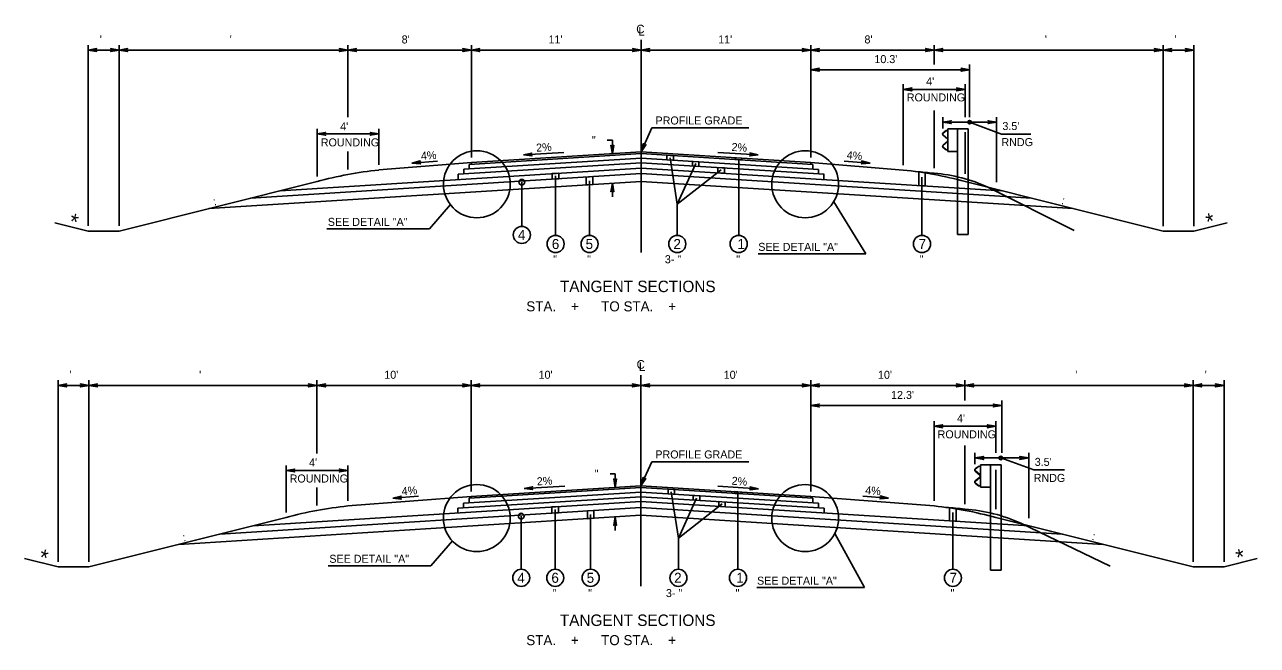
# Model space of a CAD drawing. Extents: x -540 to 1231, y -564 to 421.
# Drawn here: x -106.3 to 108.9, y -310 to -201.7 of the extents above; entities that cross this region are included whole.
import ezdxf

# ---------------------------------------------------------------- set-up
doc = ezdxf.new("R2010")
doc.units = 0
doc.layers.add('1', color=7, linetype='Continuous')
doc.layers.add('Des_ Drain_ Ftrs', color=7, linetype='Continuous')

msp = doc.modelspace()

# ---------------------------------------------------------------- linework, layer by layer
at = {"layer": '1'}
for p, q in [((1.3, -241.47), (1.3, -204.38)), ((-95.24, -236.84), (-95.24, -205.26)), ((-89.85, -206.14), (-95.24, -206.14)), ((-89.85, -236.84), (-89.85, -205.26)), ((-49.89, -206.14), (-89.85, -206.14)), ((-49.89, -217.88), (-49.89, -205.26)), ((-28.33, -206.14), (-49.89, -206.14)), ((-28.33, -224.9), (-28.33, -205.26)), ((1.3, -206.14), (-28.33, -206.14)), ((1.3, -206.14), (30.94, -206.14)), ((30.94, -224.9), (30.94, -205.26)), ((30.94, -206.14), (52.49, -206.14)), ((52.49, -208.69), (52.49, -205.26)), ((52.49, -206.14), (92.45, -206.14)), ((92.45, -236.85), (92.45, -205.26)), ((92.45, -206.14), (97.84, -206.14)), ((97.84, -236.85), (97.84, -205.26)), ((58.68, -217.84), (58.68, -208.69)), ((30.93, -209.57), (58.68, -209.57)), ((-89.85, -233.73), (-89.85, -212.26)), ((47.1, -226.2), (47.1, -212.12)), ((47.1, -213), (57.88, -213)), ((57.88, -217.84), (57.88, -212.12)), ((52.49, -226.75), (52.49, -216.67)), ((53.99, -219.8), (53.99, -217.84)), ((53.99, -218.72), (63.37, -218.72)), ((58.68, -218.72), (64.24, -220.8)), ((63.37, -229.21), (63.37, -217.84)), ((-55.26, -228.2), (-55.26, -219.89)), ((-44.49, -220.77), (-55.26, -220.77)), ((-44.49, -226.19), (-44.49, -219.89)), ((1.3, -223.92), (3.21, -219.72)), ((20.13, -219.72), (3.21, -219.72)), ((54.06, -221.01), (54.79, -221.65)), ((54.59, -220.19), (54.07, -220.58)), ((54.08, -220.99), (54.81, -221.63)), ((54.6, -220.22), (54.09, -220.61)), ((54.9, -220.14), (54.59, -220.19)), ((54.9, -220.17), (54.6, -220.22)), ((54.9, -219.91), (54.9, -223.84)), ((54.9, -219.91), (56.59, -219.91)), ((56.59, -219.91), (56.59, -238.31)), ((58.41, -219.91), (56.59, -219.91)), ((57.88, -227.72), (57.88, -220.48)), ((58.41, -219.91), (58.41, -238.31)), ((64.24, -220.8), (69.39, -220.8)), ((-49.89, -226.97), (-49.89, -223.83)), ((-3.71, -221.86), (-4.59, -221.86)), ((-3.71, -221.86), (-3.71, -224.23)), ((54.79, -222.1), (54.06, -222.74)), ((54.07, -223.17), (54.59, -223.56)), ((54.81, -222.12), (54.08, -222.76)), ((54.09, -223.14), (54.6, -223.53)), ((54.59, -223.56), (54.9, -223.61)), ((54.6, -223.53), (54.9, -223.58)), ((54.87, -221.84), (54.87, -221.91)), ((54.9, -221.84), (54.9, -221.91)), ((54.9, -223.84), (56.59, -223.84)), ((-44.49, -227.07), (-28.33, -225.77)), ((-38.7, -225.86), (-34.22, -225.5)), ((-30.64, -227.81), (1.3, -225.8)), ((-29.67, -226.95), (1.3, -225.01)), ((-28.69, -226.1), (1.3, -224.21)), ((-28.33, -225.77), (1.3, -223.91)), ((-28.33, -226.07), (-28.33, -225.77)), ((-12.16, -224), (-19.24, -224.45)), ((30.94, -225.78), (1.3, -223.92)), ((31.3, -226.1), (1.3, -224.21)), ((32.27, -226.96), (1.3, -225.01)), ((33.26, -227.82), (1.3, -225.81)), ((5.83, -224.5), (5.83, -225.29)), ((6.4, -224.95), (7.63, -233.04)), ((10.85, -225.95), (7.63, -233.04)), ((14.71, -224), (21.78, -224.45)), ((18.35, -225.16), (18.35, -238.5)), ((47.1, -227.08), (30.94, -225.78)), ((30.94, -226.08), (30.94, -225.78)), ((41.29, -225.86), (36.8, -225.5)), ((-66.88, -231.98), (1.3, -227.7)), ((-61.71, -230.69), (1.3, -226.73)), ((-30.64, -227.81), (-30.64, -228.74)), ((-29.67, -226.95), (-29.67, -227.75)), ((-28.69, -226.1), (-28.69, -226.89)), ((-13.62, -228.11), (-13.62, -238.5)), ((64.32, -230.7), (1.3, -226.73)), ((69.48, -231.99), (1.3, -227.7)), ((15.3, -227.04), (7.63, -233.04)), ((31.3, -226.1), (31.3, -226.88)), ((32.27, -226.96), (32.27, -227.75)), ((33.24, -227.82), (33.24, -228.74)), ((53.99, -227.86), (53.99, -227.86)), ((-55.26, -229.08), (-89.85, -237.72)), ((-74.17, -233.8), (1.3, -229.06)), ((-19.52, -229.2), (-19.52, -236.91)), ((-7.69, -228.94), (-7.69, -238.5)), ((-3.71, -229.38), (-3.71, -231.75)), ((76.77, -233.81), (1.3, -229.06)), ((50.36, -228.33), (50.36, -238.5)), ((57.88, -229.09), (92.45, -237.73)), ((61.87, -230.09), (76.93, -237.61)), ((-35.65, -237.32), (-32, -233.1)), ((7.63, -233.04), (7.63, -238.5)), ((34.95, -232.6), (40.55, -241.68)), ((-101.07, -236.26), (-95.24, -237.72)), ((103.67, -236.27), (97.84, -237.73)), ((-89.85, -237.72), (-95.24, -237.72)), ((-53.58, -237.32), (-35.65, -237.32)), ((58.41, -238.31), (56.59, -238.31)), ((92.45, -237.73), (97.84, -237.73)), ((21.76, -241.68), (40.55, -241.68)), ((-100.51, -295.43), (-100.51, -263.77)), ((-95.12, -264.65), (-100.51, -264.65)), ((-95.12, -295.43), (-95.12, -263.77)), ((-55.29, -264.65), (-95.12, -264.65)), ((-55.29, -276.52), (-55.29, -263.77)), ((-28.34, -264.65), (-55.29, -264.65)), ((-28.34, -283.15), (-28.34, -263.77)), ((1.29, -264.65), (-28.34, -264.65)), ((1.29, -299.71), (1.29, -262.89)), ((1.29, -264.65), (30.93, -264.65)), ((30.93, -283.15), (30.93, -263.77)), ((30.93, -264.65), (57.87, -264.65)), ((57.87, -267.29), (57.87, -263.77)), ((57.87, -264.65), (97.71, -264.65)), ((97.71, -295.43), (97.71, -263.77)), ((97.71, -264.65), (103.1, -264.65)), ((103.1, -295.43), (103.1, -263.77)), ((30.92, -268.17), (64.29, -268.17)), ((64.29, -276.44), (64.29, -267.29)), ((52.48, -284.81), (52.48, -270.91)), ((63.25, -276.44), (63.25, -270.91)), ((52.48, -271.79), (63.25, -271.79)), ((57.87, -285.35), (57.87, -275.15)), ((59.6, -278.39), (59.6, -276.44)), ((59.6, -277.32), (68.99, -277.32)), ((64.12, -277.32), (69.88, -279.4)), ((68.99, -287.81), (68.99, -276.44)), ((-60.66, -286.82), (-60.66, -278.62)), ((-49.89, -279.5), (-60.66, -279.5)), ((-49.89, -284.81), (-49.89, -278.62)), ((1.29, -282.16), (3.19, -277.99)), ((20.11, -277.99), (3.19, -277.99)), ((59.67, -279.61), (60.43, -280.25)), ((60.22, -278.79), (59.69, -279.18)), ((59.69, -279.59), (60.45, -280.23)), ((60.23, -278.82), (59.7, -279.2)), ((60.55, -278.74), (60.22, -278.79)), ((60.55, -278.77), (60.23, -278.82)), ((60.55, -278.51), (60.55, -282.44)), ((60.55, -278.51), (62.3, -278.51)), ((62.3, -278.51), (62.3, -296.9)), ((64.19, -278.51), (62.3, -278.51)), ((63.25, -286.27), (63.25, -279.39)), ((64.19, -278.51), (64.19, -296.9)), ((69.88, -279.4), (75.23, -279.4)), ((-3.21, -280.08), (-4.09, -280.08)), ((-3.21, -280.08), (-3.21, -282.45)), ((60.43, -280.7), (59.67, -281.33)), ((60.45, -280.72), (59.69, -281.36)), ((59.69, -281.77), (60.22, -282.16)), ((59.7, -281.74), (60.23, -282.13)), ((60.52, -280.44), (60.52, -280.51)), ((60.55, -280.44), (60.55, -280.51)), ((-55.29, -285.59), (-55.29, -282.47)), ((-49.89, -285.69), (-28.35, -284.03)), ((-42.06, -284.34), (-37.58, -283.99)), ((-30.69, -286.09), (1.29, -284.08)), ((-29.7, -285.22), (1.29, -283.27)), ((-28.71, -284.35), (1.29, -282.46)), ((-28.35, -284.03), (1.29, -282.16)), ((-28.35, -284.33), (-28.35, -284.03)), ((-12.03, -282.22), (-19.11, -282.67)), ((30.93, -284.03), (1.29, -282.16)), ((31.29, -284.35), (1.29, -282.46)), ((32.28, -285.22), (1.29, -283.27)), ((33.28, -286.09), (1.29, -284.08)), ((6.59, -283.2), (7.83, -291.3)), ((14.72, -282.25), (21.8, -282.7)), ((18.23, -283.41), (18.23, -296.74)), ((30.93, -284.33), (30.93, -284.03)), ((52.48, -285.69), (30.93, -284.03)), ((44.53, -284.31), (40.04, -283.97)), ((60.22, -282.16), (60.55, -282.21)), ((60.23, -282.13), (60.55, -282.18)), ((60.55, -282.44), (62.3, -282.44)), ((-72.23, -290.59), (1.29, -285.97)), ((-66.46, -289.15), (1.29, -284.89)), ((-30.69, -286.09), (-30.69, -286.9)), ((-29.7, -285.22), (-29.7, -286.03)), ((-28.71, -284.35), (-28.71, -285.16)), ((69.05, -289.15), (1.29, -284.89)), ((74.82, -290.59), (1.29, -285.97)), ((10.99, -284.33), (7.83, -291.3)), ((15.44, -285.34), (7.83, -291.3)), ((31.29, -284.35), (31.29, -285.16)), ((32.28, -285.22), (32.28, -286.04)), ((33.27, -286.09), (33.27, -286.91)), ((-60.66, -287.7), (-95.12, -296.31)), ((-79.44, -292.39), (1.29, -287.32)), ((-19.62, -287.45), (-19.62, -296.74)), ((-13.68, -286.33), (-13.68, -296.74)), ((-7.5, -287.16), (-7.5, -296.74)), ((-3.21, -287.6), (-3.21, -289.97)), ((82.02, -292.39), (1.29, -287.32)), ((55.76, -286.84), (55.76, -296.74)), ((59.6, -286.45), (59.6, -286.45)), ((63.25, -287.7), (97.71, -296.31)), ((35.13, -290.51), (40.33, -299.94)), ((67.6, -288.69), (83.22, -296.21)), ((-35.38, -296.12), (-31.64, -291.8)), ((7.83, -291.3), (7.83, -296.74)), ((-106.34, -294.85), (-100.51, -296.31)), ((108.92, -294.86), (103.1, -296.31)), ((-95.12, -296.31), (-100.51, -296.31)), ((-53.31, -296.12), (-35.38, -296.12)), ((64.19, -296.9), (62.3, -296.9)), ((97.71, -296.31), (103.1, -296.31)), ((21.55, -299.94), (40.33, -299.94))]:
    msp.add_line(p, q, dxfattribs=at)
for points in [[(5.83, -224.5), (6.97, -224.57), (6.97, -225.37), (5.83, -225.29)], [(10.28, -225.57), (11.42, -225.65), (11.42, -226.44), (10.28, -226.37)], [(17.78, -224.95), (18.92, -225.03), (18.92, -225.32), (17.78, -225.25)], [(-14.19, -227.7), (-13.04, -227.63), (-13.04, -228.6), (-14.19, -228.67)], [(14.72, -227.58), (14.72, -226.65), (15.87, -226.72), (15.87, -227.65)], [(49.79, -227.41), (50.92, -227.58), (50.92, -229.86), (49.79, -229.78)], [(-8.26, -228.3), (-7.11, -228.23), (-7.11, -229.59), (-8.26, -229.66)], [(6.02, -282.76), (7.17, -282.83), (7.17, -283.64), (6.02, -283.57)], [(10.41, -283.85), (11.56, -283.92), (11.56, -284.73), (10.41, -284.65)], [(17.66, -283.19), (18.81, -283.26), (18.81, -283.56), (17.66, -283.49)], [(-14.26, -285.87), (-13.11, -285.79), (-13.11, -286.87), (-14.26, -286.95)], [(14.86, -284.93), (16.01, -285.01), (16.01, -285.82), (14.86, -285.74)], [(55.18, -288.28), (55.18, -286.04), (56.33, -286.2), (56.33, -288.35)], [(-8.07, -286.56), (-6.93, -286.49), (-6.93, -287.83), (-8.07, -287.91)]]:
    msp.add_lwpolyline(points, close=True, dxfattribs=at)
for centre, radius in [((58.68, -218.73), 0.3), ((-27.37, -229.56), 5.84), ((29.97, -229.56), 5.84), ((-19.52, -229.2), 0.5), ((-19.52, -238.4), 1.49), ((-13.62, -239.98), 1.49), ((-7.69, -239.98), 1.49), ((7.63, -239.98), 1.49), ((18.35, -239.98), 1.49), ((50.36, -239.98), 1.49), ((-27.38, -287.8), 5.84), ((29.96, -287.8), 5.84), ((-19.62, -287.45), 0.5), ((-19.62, -298.23), 1.49), ((-13.68, -298.23), 1.49), ((-7.5, -298.23), 1.49), ((7.83, -298.23), 1.49), ((18.23, -298.23), 1.49), ((55.76, -298.23), 1.49)]:
    msp.add_circle(centre, radius, dxfattribs=at)
for centre, radius, start, end in [((54.24, -220.8), 0.278, 126.9799, 229.021), ((54.24, -220.8), 0.249, 126.9799, 229.021), ((54.62, -221.84), 0.249, 0, 49.0365), ((54.62, -221.84), 0.278, 0, 49.0365), ((54.24, -222.95), 0.278, 130.979, 233.0201), ((54.24, -222.95), 0.249, 130.979, 233.0201), ((54.62, -221.91), 0.249, 310.9635, 0), ((54.62, -221.91), 0.278, 310.9635, 0), ((-37.61, -293.91), 67.19, 95.8795, 105.2381), ((40.22, -293.91), 67.19, 74.7619, 84.1205), ((41.67, -328.3), 101.24, 83.8633, 85.6775), ((50.37, -254.92), 27.37, 65.1374, 85.5513), ((-43.01, -352.53), 67.19, 95.8795, 105.2381), ((45.59, -352.53), 67.19, 74.7598, 84.1183)]:
    msp.add_arc(centre, radius, start, end, dxfattribs=at)
msp.add_ellipse((64.12, -277.32), major_axis=(-0.311, 0), ratio=0.964041, dxfattribs=at)
for centre, major_axis, start_param, end_param in [((59.86, -279.4), (-0.288, 0), 5.35781, 7.138763), ((59.86, -279.4), (-0.258, 0), 5.35781, 7.138763), ((59.86, -281.54), (-0.288, 0), 5.427608, 7.208561), ((59.86, -281.54), (-0.258, 0), 5.427608, 7.208561), ((60.26, -280.44), (0.258, 0), 0, 0.855848), ((60.26, -280.51), (0.258, 0), 5.427337, 6.283185), ((60.26, -280.44), (0.288, 0), 0, 0.855848), ((60.26, -280.51), (0.288, 0), 5.427337, 6.283185), ((46.64, -386.9), (105.02, 0), 1.463691, 1.495354), ((55.67, -313.52), (28.39, 0), 1.136862, 1.493152)]:
    msp.add_ellipse(centre, major_axis=major_axis, ratio=0.964041, start_param=start_param, end_param=end_param, dxfattribs=at)
at = {"layer": 'Des_ Drain_ Ftrs'}
for points in [[(-95.24, -206.14), (-93.76, -206.39), (-94.05, -206.14), (-93.76, -205.89)], [(-89.85, -206.14), (-91.34, -206.39), (-91.05, -206.14), (-91.34, -205.89)], [(-89.85, -206.14), (-88.37, -206.39), (-88.66, -206.14), (-88.37, -205.89)], [(-49.89, -206.14), (-51.38, -206.39), (-51.08, -206.14), (-51.38, -205.89)], [(-49.89, -206.14), (-48.4, -206.39), (-48.69, -206.14), (-48.4, -205.89)], [(-28.33, -206.14), (-29.82, -206.39), (-29.53, -206.14), (-29.82, -205.89)], [(-28.33, -206.14), (-26.85, -206.39), (-27.14, -206.14), (-26.85, -205.89)], [(1.3, -206.14), (-0.19, -206.39), (0.11, -206.14), (-0.19, -205.89)], [(1.3, -206.14), (2.79, -206.39), (2.5, -206.14), (2.79, -205.89)], [(30.94, -206.14), (29.45, -206.39), (29.74, -206.14), (29.45, -205.89)], [(30.94, -206.14), (32.43, -206.39), (32.13, -206.14), (32.43, -205.89)], [(52.49, -206.14), (51, -206.39), (51.3, -206.14), (51, -205.89)], [(52.49, -206.14), (53.98, -206.39), (53.68, -206.14), (53.98, -205.89)], [(92.45, -206.14), (90.96, -206.39), (91.26, -206.14), (90.96, -205.89)], [(92.45, -206.14), (93.94, -206.39), (93.65, -206.14), (93.94, -205.89)], [(97.84, -206.14), (96.35, -206.39), (96.65, -206.14), (96.35, -205.89)], [(30.93, -209.57), (32.42, -209.82), (32.13, -209.57), (32.42, -209.32)], [(58.68, -209.57), (57.19, -209.82), (57.49, -209.57), (57.19, -209.32)], [(47.1, -213), (48.59, -213.25), (48.29, -213), (48.59, -212.75)], [(57.88, -213), (56.39, -213.25), (56.68, -213), (56.39, -212.75)], [(53.99, -218.72), (55.48, -218.97), (55.18, -218.72), (55.48, -218.48)], [(63.37, -218.72), (61.89, -218.97), (62.18, -218.72), (61.89, -218.48)], [(-55.26, -220.77), (-53.78, -221.02), (-54.07, -220.77), (-53.78, -220.52)], [(-44.49, -220.77), (-45.98, -221.02), (-45.68, -220.77), (-45.98, -220.52)], [(-3.71, -224.23), (-3.46, -222.74), (-3.71, -223.04), (-3.96, -222.74)], [(1.3, -223.92), (2.14, -222.67), (1.8, -222.83), (1.69, -222.46)], [(-38.7, -225.86), (-37.2, -225.99), (-37.51, -225.76), (-37.24, -225.49)], [(-19.24, -224.45), (-17.73, -224.6), (-18.04, -224.37), (-17.77, -224.11)], [(21.78, -224.45), (20.28, -224.6), (20.59, -224.37), (20.31, -224.1)], [(41.29, -225.86), (39.78, -225.99), (40.1, -225.76), (39.82, -225.49)], [(-3.71, -229.38), (-3.46, -230.87), (-3.71, -230.58), (-3.96, -230.87)], [(-100.51, -264.65), (-99.02, -264.9), (-99.31, -264.65), (-99.02, -264.4)], [(-95.12, -264.65), (-96.61, -264.9), (-96.31, -264.65), (-96.61, -264.4)], [(-95.12, -264.65), (-93.63, -264.9), (-93.93, -264.65), (-93.63, -264.4)], [(-55.29, -264.65), (-56.77, -264.9), (-56.48, -264.65), (-56.77, -264.4)], [(-55.29, -264.65), (-53.8, -264.9), (-54.09, -264.65), (-53.8, -264.4)], [(-28.34, -264.65), (-29.83, -264.9), (-29.54, -264.65), (-29.83, -264.4)], [(-28.34, -264.65), (-26.86, -264.9), (-27.15, -264.65), (-26.86, -264.4)], [(1.29, -264.65), (-0.2, -264.9), (0.1, -264.65), (-0.2, -264.4)], [(1.29, -264.65), (2.78, -264.9), (2.48, -264.65), (2.78, -264.4)], [(30.93, -264.65), (29.44, -264.9), (29.73, -264.65), (29.44, -264.4)], [(30.93, -264.65), (32.41, -264.9), (32.12, -264.65), (32.41, -264.4)], [(57.87, -264.65), (56.38, -264.9), (56.67, -264.65), (56.38, -264.4)], [(57.87, -264.65), (59.36, -264.9), (59.06, -264.65), (59.36, -264.4)], [(97.71, -264.65), (96.22, -264.9), (96.51, -264.65), (96.22, -264.4)], [(97.71, -264.65), (99.2, -264.9), (98.9, -264.65), (99.2, -264.4)], [(103.1, -264.65), (101.61, -264.9), (101.9, -264.65), (101.61, -264.4)], [(30.92, -268.17), (32.41, -268.42), (32.12, -268.17), (32.41, -267.92)], [(64.29, -268.17), (62.8, -268.42), (63.1, -268.17), (62.8, -267.92)], [(52.48, -271.79), (53.97, -272.04), (53.67, -271.79), (53.97, -271.55)], [(63.25, -271.79), (61.77, -272.04), (62.06, -271.79), (61.77, -271.55)], [(59.6, -277.32), (61.15, -277.57), (60.84, -277.32), (61.15, -277.08)], [(68.99, -277.32), (67.44, -277.57), (67.75, -277.32), (67.44, -277.08)], [(-60.66, -279.5), (-59.18, -279.75), (-59.47, -279.5), (-59.18, -279.25)], [(-49.89, -279.5), (-51.38, -279.75), (-51.08, -279.5), (-51.38, -279.25)], [(-3.21, -282.45), (-2.97, -280.96), (-3.21, -281.25), (-3.46, -280.96)], [(1.29, -282.16), (2.13, -280.91), (1.78, -281.08), (1.68, -280.7)], [(-42.06, -284.34), (-40.56, -284.48), (-40.87, -284.25), (-40.6, -283.98)], [(-19.11, -282.67), (-17.61, -282.82), (-17.92, -282.59), (-17.64, -282.33)], [(21.8, -282.7), (20.3, -282.85), (20.61, -282.62), (20.33, -282.36)], [(44.53, -284.31), (43.02, -284.45), (43.34, -284.22), (43.06, -283.95)], [(-3.21, -287.6), (-2.97, -289.09), (-3.21, -288.79), (-3.46, -289.09)]]:
    msp.add_lwpolyline(points, close=True, dxfattribs=at)

# ---------------------------------------------------------------- texts
at = {"layer": '1'}
for s, height, p in [(" '", 1.4, (-93.74, -204.99)), ("  '", 1.4, (-71.57, -204.99)), ("8'", 1.4, (-40.5, -204.99)), ("11'", 1.4, (-14.86, -204.99)), ("11'", 1.4, (14.77, -204.99)), ("8'", 1.4, (40.32, -204.99)), ("  '", 1.4, (70.78, -204.99)), (" '", 1.4, (93.95, -204.99)), ("10.3'", 1.4, (42.05, -208.42)), ("4'", 1.4, (51.1, -212.3)), ('ROUNDING', 1.4, (47.71, -215.1)), ("4'", 1.4, (-51.23, -220.15)), ('PROFILE GRADE', 1.4, (3.83, -219.13)), ("3.5'", 1.4, (64.4, -220.1)), ('ROUNDING', 1.4, (-54.62, -222.95)), ('RNDG', 1.4, (64.23, -222.9)), ('SEE DETAIL "A"', 1.4, (-53.39, -236.82)), ('4', 1.75, (-20.2, -239.27)), ('6', 1.75, (-14.28, -240.86)), ('5', 1.75, (-8.38, -240.86)), ('2', 1.75, (6.96, -240.86)), ('1', 1.75, (18.14, -240.86)), ('SEE DETAIL "A"', 1.4, (21.77, -241.18)), ('7', 1.75, (49.77, -240.86)), (' "', 1.4, (-14.56, -243.34)), (' "', 1.4, (-8.63, -243.34)), ('3- "', 1.4, (5.46, -243.34)), (' "', 1.4, (17.41, -243.34)), ('  "', 1.4, (48.92, -243.34)), ('TANGENT SECTIONS', 2, (-12.87, -248.38)), ('STA.    +      TO STA.    +     ', 1.75, (-18.73, -251.74)), (" '", 1.4, (-99.01, -263.5)), ("  '", 1.4, (-76.9, -263.5)), ("10'", 1.4, (-43.53, -263.5)), ("10'", 1.4, (-16.59, -263.5)), ("10'", 1.4, (15.74, -263.5)), ("10'", 1.4, (42.68, -263.5)), ("  '", 1.4, (76.09, -263.5)), (" '", 1.4, (99.21, -263.5)), ("12.3'", 1.4, (44.96, -267.02)), ("4'", 1.4, (56.48, -271.09)), ('ROUNDING', 1.4, (53.09, -273.89)), ("4'", 1.4, (-56.67, -278.8)), ('PROFILE GRADE', 1.4, (3.8, -277.4)), ("3.5'", 1.4, (70.05, -278.7)), ('ROUNDING', 1.4, (-60.06, -281.6)), ('RNDG', 1.4, (69.87, -281.5)), ('SEE DETAIL "A"', 1.4, (-53.13, -295.61)), ('4', 1.75, (-20.29, -299.1)), ('6', 1.75, (-14.35, -299.1)), ('5', 1.75, (-8.19, -299.1)), ('2', 1.75, (7.08, -299.1)), ('1', 1.75, (17.93, -299.1)), ('SEE DETAIL "A"', 1.4, (21.56, -299.43)), ('7', 1.75, (55.17, -299.1)), (' "', 1.4, (-14.63, -301.59)), (' "', 1.4, (-8.45, -301.59)), ('3- "', 1.4, (5.65, -301.59)), (' "', 1.4, (17.29, -301.59)), ('  "', 1.4, (54.31, -301.59)), ('TANGENT SECTIONS', 2, (-12.88, -306.63)), ('STA.    +      TO STA.    +     ', 1.75, (-18.74, -309.98))]:
    msp.add_text(s, height=height, dxfattribs=at).set_placement(p)
for s, height, rotation, p in [('  "', 1.4, 0.1438, (-8.32, -222.56)), ('4%', 1.4, 4.8672, (-37.08, -225.34)), ('2%', 1.4, 3.7237, (-16.97, -223.89)), ('2%', 1.4, 356.2763, (17.07, -223.73)), ('4%', 1.4, 355.1257, (37.17, -225.13)), (' : ', 1.4, 14.2282, (-73.74, -233.41)), (' : ', 1.4, 345.7718, (74.11, -232.86)), ('*', 2.8, 12.8479, (100.3, -237.54)), ('*', 2.8, 347.1521, (-98.76, -237.29)), ('  "', 1.4, 0.1438, (-7.83, -280.78)), ('2%', 1.4, 3.7237, (-16.85, -282.11)), ('2%', 1.4, 356.2768, (17.09, -281.98)), ('4%', 1.4, 4.703, (-40.44, -283.83)), ('4%', 1.4, 355.2917, (40.41, -283.6)), (' : ', 1.4, 345.7718, (79.43, -291.46)), (' : ', 1.4, 14.2282, (-79.07, -292.02)), ('*', 2.8, 347.1521, (-104.02, -295.88)), ('*', 2.8, 12.8479, (105.56, -296.12))]:
    msp.add_text(s, height=height, rotation=rotation, dxfattribs=at).set_placement(p)
at = {"layer": 'Des_ Drain_ Ftrs'}
for s, p in [('C', (0.46, -203.23)), ('L', (0.85, -203.63)), ('C', (0.53, -261.75)), ('L', (0.92, -262.15))]:
    msp.add_text(s, height=1.5, dxfattribs=at).set_placement(p)

doc.saveas('drawing.dxf')
